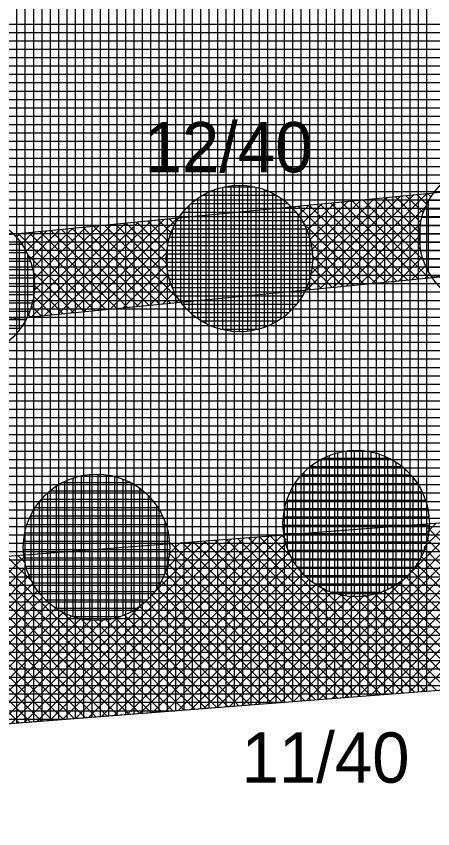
# Model space of a CAD drawing. Extents: x -566461 to -565198, y -1096301 to -1095707.
# Drawn here: x -566318.3 to -566308.34, y -1095862.29 to -1095842.88 of the extents above; entities that cross this region are included whole.
import ezdxf

# ---------------------------------------------------------------- set-up
doc = ezdxf.new("R2010")
doc.units = 0
for name, color, linetype in [('Vrstva 1', 7, 'Continuous'), ('Vrstva 40', 7, 'Continuous'), ('Vrstva 41', 7, 'Continuous'), ('Vrstva 42', 7, 'Continuous'), ('Vrstva 43', 7, 'Continuous'), ('Vrstva 44', 7, 'Continuous')]:
    doc.layers.add(name, color=color, linetype=linetype)

msp = doc.modelspace()

# ---------------------------------------------------------------- linework, layer by layer
at = {"layer": 'Vrstva 1'}
msp.add_line((-566351.09, -1095862.29), (-566300.24, -1095858.37), dxfattribs=at)
at = {"layer": 'Vrstva 41'}
for p, q in [((-566308.802, -1095847.155), (-566311.03, -1095849.384)), ((-566308.488, -1095847.125), (-566310.716, -1095849.353)), ((-566308.714, -1095847.147), (-566308.478, -1095847.384)), ((-566308.457, -1095847.122), (-566308.376, -1095847.202)), ((-566310.683, -1095847.339), (-566311.352, -1095848.009)), ((-566309.115, -1095847.186), (-566311.343, -1095849.414)), ((-566310.369, -1095847.309), (-566311.281, -1095848.221)), ((-566309.429, -1095847.217), (-566311.263, -1095849.051)), ((-566310.056, -1095847.278), (-566311.234, -1095848.456)), ((-566309.742, -1095847.247), (-566311.226, -1095848.732)), ((-566310.775, -1095847.348), (-566308.944, -1095849.18)), ((-566310.518, -1095847.323), (-566308.687, -1095849.154)), ((-566310.26, -1095847.298), (-566308.429, -1095849.129)), ((-566310.003, -1095847.273), (-566308.55, -1095848.725)), ((-566309.745, -1095847.248), (-566308.638, -1095848.355)), ((-566309.487, -1095847.222), (-566308.649, -1095848.061)), ((-566309.23, -1095847.197), (-566308.62, -1095847.807)), ((-566308.972, -1095847.172), (-566308.561, -1095847.583)), ((-566311.623, -1095847.431), (-566311.682, -1095847.491)), ((-566311.31, -1095847.401), (-566311.554, -1095847.645)), ((-566311.548, -1095847.424), (-566309.717, -1095849.255)), ((-566310.996, -1095847.37), (-566311.444, -1095847.818)), ((-566311.291, -1095847.399), (-566309.46, -1095849.23)), ((-566311.033, -1095847.374), (-566309.202, -1095849.205)), ((-566308.492, -1095847.411), (-566310.403, -1095849.322)), ((-566314.758, -1095847.738), (-566316.986, -1095849.966)), ((-566314.444, -1095847.707), (-566316.672, -1095849.935)), ((-566314.64, -1095847.726), (-566314.501, -1095847.866)), ((-566316.012, -1095847.86), (-566317.939, -1095849.787)), ((-566315.698, -1095847.83), (-566317.926, -1095850.058)), ((-566316.325, -1095847.891), (-566317.885, -1095849.45)), ((-566316.639, -1095847.922), (-566317.878, -1095849.161)), ((-566315.385, -1095847.799), (-566317.613, -1095850.027)), ((-566315.071, -1095847.768), (-566317.299, -1095849.996)), ((-566316.702, -1095847.928), (-566314.87, -1095849.759)), ((-566316.444, -1095847.903), (-566314.613, -1095849.734)), ((-566316.186, -1095847.877), (-566314.356, -1095849.707)), ((-566315.929, -1095847.852), (-566314.63, -1095849.15)), ((-566315.671, -1095847.827), (-566314.693, -1095848.805)), ((-566315.413, -1095847.802), (-566314.693, -1095848.522)), ((-566315.156, -1095847.777), (-566314.654, -1095848.278)), ((-566314.898, -1095847.751), (-566314.588, -1095848.061)), ((-566311.451, -1095847.805), (-566309.975, -1095849.28)), ((-566308.622, -1095847.825), (-566310.089, -1095849.292)), ((-566318.206, -1095848.075), (-566318.299, -1095848.168)), ((-566318.248, -1095848.079), (-566316.416, -1095849.91)), ((-566317.893, -1095848.044), (-566318.176, -1095848.327)), ((-566317.579, -1095848.014), (-566318.07, -1095848.504)), ((-566317.99, -1095848.054), (-566316.159, -1095849.885)), ((-566317.266, -1095847.983), (-566317.983, -1095848.7)), ((-566316.952, -1095847.952), (-566317.916, -1095848.916)), ((-566317.732, -1095848.028), (-566315.901, -1095849.86)), ((-566317.475, -1095848.003), (-566315.643, -1095849.834)), ((-566317.217, -1095847.978), (-566315.386, -1095849.809)), ((-566316.959, -1095847.953), (-566315.128, -1095849.784)), ((-566314.625, -1095848.171), (-566316.359, -1095849.904)), ((-566311.268, -1095848.27), (-566310.233, -1095849.306)), ((-566308.653, -1095848.138), (-566309.776, -1095849.261)), ((-566308.631, -1095848.399), (-566309.462, -1095849.23)), ((-566318.033, -1095848.576), (-566316.674, -1095849.935)), ((-566314.693, -1095848.521), (-566316.045, -1095849.874)), ((-566311.224, -1095848.597), (-566310.49, -1095849.331)), ((-566308.581, -1095848.631), (-566309.149, -1095849.2)), ((-566314.693, -1095848.804), (-566315.732, -1095849.843)), ((-566311.24, -1095848.863), (-566310.748, -1095849.356)), ((-566308.506, -1095848.839), (-566308.835, -1095849.169)), ((-566317.901, -1095848.991), (-566316.932, -1095849.96)), ((-566314.657, -1095849.051), (-566315.419, -1095849.812)), ((-566308.409, -1095849.026), (-566308.522, -1095849.138)), ((-566314.592, -1095849.269), (-566315.105, -1095849.782)), ((-566311.278, -1095849.108), (-566311.006, -1095849.381)), ((-566317.87, -1095849.305), (-566317.189, -1095849.986)), ((-566314.505, -1095849.465), (-566314.792, -1095849.751)), ((-566311.348, -1095849.321), (-566311.263, -1095849.406)), ((-566317.896, -1095849.561), (-566317.447, -1095850.011)), ((-566314.4, -1095849.643), (-566314.478, -1095849.721)), ((-566317.942, -1095849.799), (-566317.705, -1095850.036)), ((-566318.016, -1095850.007), (-566317.962, -1095850.061)), ((-566307.033, -1095854.9), (-566311.36, -1095859.227)), ((-566306.727, -1095854.877), (-566311.053, -1095859.204)), ((-566306.42, -1095854.853), (-566310.747, -1095859.18)), ((-566306.114, -1095854.83), (-566310.44, -1095859.156)), ((-566305.807, -1095854.806), (-566310.134, -1095859.133)), ((-566307.646, -1095854.948), (-566311.973, -1095859.274)), ((-566307.339, -1095854.924), (-566311.666, -1095859.251)), ((-566305.725, -1095855.007), (-566309.827, -1095859.109)), ((-566307.952, -1095854.971), (-566308.544, -1095855.563)), ((-566308.259, -1095854.995), (-566308.469, -1095855.205)), ((-566308.459, -1095855.103), (-566304.837, -1095858.724)), ((-566312.243, -1095855.302), (-566316.57, -1095859.629)), ((-566311.936, -1095855.278), (-566316.263, -1095859.605)), ((-566312.221, -1095855.3), (-566311.664, -1095855.858)), ((-566311.958, -1095855.28), (-566311.846, -1095855.393)), ((-566305.656, -1095855.221), (-566309.521, -1095859.085)), ((-566313.469, -1095855.397), (-566317.796, -1095859.723)), ((-566313.162, -1095855.373), (-566317.489, -1095859.7)), ((-566312.856, -1095855.349), (-566317.183, -1095859.676)), ((-566312.549, -1095855.326), (-566316.876, -1095859.652)), ((-566311.829, -1095855.454), (-566315.957, -1095859.582)), ((-566313.775, -1095855.42), (-566315.074, -1095856.719)), ((-566314.082, -1095855.444), (-566314.717, -1095856.079)), ((-566314.388, -1095855.467), (-566314.658, -1095855.737)), ((-566314.584, -1095855.483), (-566310.877, -1095859.19)), ((-566314.322, -1095855.462), (-566310.614, -1095859.17)), ((-566314.059, -1095855.442), (-566310.352, -1095859.15)), ((-566313.797, -1095855.422), (-566310.089, -1095859.129)), ((-566313.534, -1095855.402), (-566309.827, -1095859.109)), ((-566313.271, -1095855.381), (-566309.564, -1095859.089)), ((-566313.009, -1095855.361), (-566309.301, -1095859.069)), ((-566312.746, -1095855.341), (-566309.039, -1095859.048)), ((-566312.484, -1095855.321), (-566308.776, -1095859.028)), ((-566305.566, -1095855.413), (-566309.214, -1095859.062)), ((-566308.485, -1095855.359), (-566305.1, -1095858.745)), ((-566311.757, -1095855.665), (-566315.65, -1095859.558)), ((-566314.653, -1095855.697), (-566311.14, -1095859.21)), ((-566305.457, -1095855.587), (-566308.908, -1095859.038)), ((-566308.55, -1095855.578), (-566305.362, -1095858.765)), ((-566318.105, -1095855.79), (-566322.393, -1095860.078)), ((-566319.836, -1095855.887), (-566316.129, -1095859.595)), ((-566319.574, -1095855.867), (-566315.866, -1095859.575)), ((-566319.311, -1095855.847), (-566315.604, -1095859.554)), ((-566319.049, -1095855.827), (-566315.341, -1095859.534)), ((-566318.786, -1095855.806), (-566315.079, -1095859.514)), ((-566318.523, -1095855.786), (-566317.905, -1095856.404)), ((-566318.261, -1095855.766), (-566318.077, -1095855.949)), ((-566311.665, -1095855.855), (-566315.344, -1095859.534)), ((-566308.635, -1095855.775), (-566305.625, -1095858.785)), ((-566305.33, -1095855.743), (-566308.602, -1095859.015)), ((-566318.057, -1095856.025), (-566322.086, -1095860.054)), ((-566321.412, -1095856.009), (-566317.705, -1095859.716)), ((-566321.149, -1095855.989), (-566317.442, -1095859.696)), ((-566320.887, -1095855.968), (-566317.179, -1095859.676)), ((-566320.624, -1095855.948), (-566316.917, -1095859.656)), ((-566320.362, -1095855.928), (-566316.654, -1095859.635)), ((-566320.099, -1095855.908), (-566316.392, -1095859.615)), ((-566311.552, -1095856.025), (-566315.037, -1095859.511)), ((-566314.683, -1095855.95), (-566311.402, -1095859.23)), ((-566308.739, -1095855.954), (-566305.888, -1095858.805)), ((-566317.986, -1095856.237), (-566321.78, -1095860.03)), ((-566321.472, -1095856.232), (-566317.967, -1095859.737)), ((-566314.748, -1095856.168), (-566311.665, -1095859.251)), ((-566311.423, -1095856.179), (-566314.731, -1095859.487)), ((-566308.998, -1095856.26), (-566306.413, -1095858.846)), ((-566308.86, -1095856.115), (-566306.15, -1095858.826)), ((-566321.524, -1095856.463), (-566318.23, -1095859.757)), ((-566317.894, -1095856.427), (-566321.473, -1095860.007)), ((-566314.834, -1095856.364), (-566311.927, -1095859.271)), ((-566311.277, -1095856.316), (-566314.424, -1095859.463)), ((-566311.115, -1095856.437), (-566314.118, -1095859.44)), ((-566309.153, -1095856.389), (-566306.675, -1095858.866)), ((-566317.783, -1095856.599), (-566321.167, -1095859.983)), ((-566314.939, -1095856.542), (-566312.19, -1095859.291)), ((-566310.936, -1095856.54), (-566313.811, -1095859.416)), ((-566310.737, -1095856.625), (-566313.505, -1095859.393)), ((-566309.607, -1095856.626), (-566312.279, -1095859.298)), ((-566311.028, -1095856.494), (-566308.514, -1095859.008)), ((-566309.728, -1095856.662), (-566307.463, -1095858.927)), ((-566309.516, -1095856.591), (-566307.201, -1095858.907)), ((-566309.324, -1095856.5), (-566306.938, -1095858.886)), ((-566317.654, -1095856.754), (-566320.86, -1095859.96)), ((-566315.199, -1095856.847), (-566312.715, -1095859.332)), ((-566315.061, -1095856.703), (-566312.453, -1095859.311)), ((-566310.516, -1095856.687), (-566313.199, -1095859.369)), ((-566310.264, -1095856.717), (-566312.892, -1095859.345)), ((-566309.974, -1095856.711), (-566312.586, -1095859.322)), ((-566310.563, -1095856.676), (-566308.251, -1095858.988)), ((-566310.237, -1095856.719), (-566307.988, -1095858.967)), ((-566309.964, -1095856.709), (-566307.726, -1095858.947)), ((-566317.51, -1095856.892), (-566320.554, -1095859.936)), ((-566317.348, -1095857.013), (-566320.247, -1095859.912)), ((-566315.231, -1095856.876), (-566318.102, -1095859.747)), ((-566315.354, -1095856.976), (-566312.978, -1095859.352)), ((-566317.17, -1095857.118), (-566319.941, -1095859.889)), ((-566316.973, -1095857.204), (-566319.634, -1095859.865)), ((-566315.871, -1095857.233), (-566318.409, -1095859.771)), ((-566317.214, -1095857.095), (-566314.816, -1095859.494)), ((-566315.93, -1095857.248), (-566313.766, -1095859.413)), ((-566315.718, -1095857.178), (-566313.503, -1095859.392)), ((-566315.527, -1095857.086), (-566313.24, -1095859.372)), ((-566316.755, -1095857.269), (-566319.328, -1095859.841)), ((-566316.507, -1095857.304), (-566319.021, -1095859.818)), ((-566316.223, -1095857.302), (-566318.715, -1095859.794)), ((-566316.759, -1095857.267), (-566314.553, -1095859.473)), ((-566316.437, -1095857.307), (-566314.291, -1095859.453)), ((-566316.165, -1095857.296), (-566314.028, -1095859.433))]:
    msp.add_line(p, q, dxfattribs=at)
at = {"layer": 'Vrstva 42'}
for points in [[(-566353.532, -1095851.528), (-566353.085, -1095853.494), (-566302.553, -1095848.555), (-566303.017, -1095846.59)], [(-566351.98, -1095858.365), (-566351.09, -1095862.29), (-566300.24, -1095858.37), (-566301.163, -1095854.448)]]:
    msp.add_lwpolyline(points, close=True, dxfattribs=at)
at = {"layer": 'Vrstva 43'}
for p, q in [((-566309.09, -1095837.638), (-566309.09, -1095859.052)), ((-566308.89, -1095837.619), (-566308.89, -1095859.037)), ((-566308.69, -1095837.599), (-566308.69, -1095859.021)), ((-566308.49, -1095837.58), (-566308.49, -1095859.006)), ((-566311.09, -1095837.834), (-566311.09, -1095859.206)), ((-566310.89, -1095837.814), (-566310.89, -1095859.191)), ((-566310.69, -1095837.795), (-566310.69, -1095859.176)), ((-566310.49, -1095837.775), (-566310.49, -1095859.16)), ((-566310.29, -1095837.756), (-566310.29, -1095859.145)), ((-566310.09, -1095837.736), (-566310.09, -1095859.129)), ((-566309.89, -1095837.717), (-566309.89, -1095859.114)), ((-566309.69, -1095837.697), (-566309.69, -1095859.098)), ((-566309.49, -1095837.677), (-566309.49, -1095859.083)), ((-566309.29, -1095837.658), (-566309.29, -1095859.068)), ((-566313.09, -1095838.029), (-566313.09, -1095859.361)), ((-566312.89, -1095838.01), (-566312.89, -1095859.345)), ((-566312.69, -1095837.99), (-566312.69, -1095859.33)), ((-566312.49, -1095837.971), (-566312.49, -1095859.314)), ((-566312.29, -1095837.951), (-566312.29, -1095859.299)), ((-566312.09, -1095837.932), (-566312.09, -1095859.284)), ((-566311.89, -1095837.912), (-566311.89, -1095859.268)), ((-566311.69, -1095837.893), (-566311.69, -1095859.253)), ((-566311.49, -1095837.873), (-566311.49, -1095859.237)), ((-566311.29, -1095837.853), (-566311.29, -1095859.222)), ((-566315.09, -1095838.225), (-566315.09, -1095859.515)), ((-566314.89, -1095838.205), (-566314.89, -1095859.499)), ((-566314.69, -1095838.186), (-566314.69, -1095859.484)), ((-566314.49, -1095838.166), (-566314.49, -1095859.469)), ((-566314.29, -1095838.147), (-566314.29, -1095859.453)), ((-566314.09, -1095838.127), (-566314.09, -1095859.438)), ((-566313.89, -1095838.108), (-566313.89, -1095859.422)), ((-566313.69, -1095838.088), (-566313.69, -1095859.407)), ((-566313.49, -1095838.068), (-566313.49, -1095859.391)), ((-566313.29, -1095838.049), (-566313.29, -1095859.376)), ((-566317.09, -1095838.42), (-566317.09, -1095859.669)), ((-566316.89, -1095838.401), (-566316.89, -1095859.654)), ((-566316.69, -1095838.381), (-566316.69, -1095859.638)), ((-566316.49, -1095838.362), (-566316.49, -1095859.623)), ((-566316.29, -1095838.342), (-566316.29, -1095859.607)), ((-566316.09, -1095838.323), (-566316.09, -1095859.592)), ((-566315.89, -1095838.303), (-566315.89, -1095859.576)), ((-566315.69, -1095838.284), (-566315.69, -1095859.561)), ((-566315.49, -1095838.264), (-566315.49, -1095859.546)), ((-566315.29, -1095838.244), (-566315.29, -1095859.53)), ((-566318.29, -1095838.538), (-566318.29, -1095859.761)), ((-566318.09, -1095838.518), (-566318.09, -1095859.746)), ((-566317.89, -1095838.499), (-566317.89, -1095859.731)), ((-566317.69, -1095838.479), (-566317.69, -1095859.715)), ((-566317.49, -1095838.46), (-566317.49, -1095859.7)), ((-566317.29, -1095838.44), (-566317.29, -1095859.684)), ((-566355.45, -1095843.07), (-566303.849, -1095843.07)), ((-566355.405, -1095843.27), (-566303.802, -1095843.27)), ((-566355.36, -1095843.47), (-566303.755, -1095843.47)), ((-566355.314, -1095843.67), (-566303.708, -1095843.67)), ((-566355.269, -1095843.87), (-566303.661, -1095843.87)), ((-566355.223, -1095844.07), (-566303.613, -1095844.07)), ((-566355.178, -1095844.27), (-566303.566, -1095844.27)), ((-566355.133, -1095844.47), (-566303.519, -1095844.47)), ((-566355.087, -1095844.67), (-566303.472, -1095844.67)), ((-566355.042, -1095844.87), (-566303.425, -1095844.87)), ((-566354.997, -1095845.07), (-566303.378, -1095845.07)), ((-566354.951, -1095845.27), (-566303.33, -1095845.27)), ((-566354.906, -1095845.47), (-566303.283, -1095845.47)), ((-566354.861, -1095845.67), (-566303.236, -1095845.67)), ((-566354.815, -1095845.87), (-566303.189, -1095845.87)), ((-566354.77, -1095846.07), (-566303.142, -1095846.07)), ((-566354.724, -1095846.27), (-566303.094, -1095846.27)), ((-566354.679, -1095846.47), (-566303.047, -1095846.47)), ((-566354.634, -1095846.67), (-566303, -1095846.67)), ((-566354.588, -1095846.87), (-566302.953, -1095846.87)), ((-566354.543, -1095847.07), (-566302.906, -1095847.07)), ((-566354.498, -1095847.27), (-566302.859, -1095847.27)), ((-566354.452, -1095847.47), (-566302.811, -1095847.47)), ((-566354.407, -1095847.67), (-566302.764, -1095847.67)), ((-566354.361, -1095847.87), (-566302.717, -1095847.87)), ((-566354.316, -1095848.07), (-566302.67, -1095848.07)), ((-566354.271, -1095848.27), (-566302.623, -1095848.27)), ((-566354.225, -1095848.47), (-566302.575, -1095848.47)), ((-566354.18, -1095848.67), (-566302.528, -1095848.67)), ((-566354.135, -1095848.87), (-566302.481, -1095848.87)), ((-566354.089, -1095849.07), (-566302.434, -1095849.07)), ((-566354.044, -1095849.27), (-566302.387, -1095849.27)), ((-566353.998, -1095849.47), (-566302.34, -1095849.47)), ((-566353.953, -1095849.67), (-566302.292, -1095849.67)), ((-566353.908, -1095849.87), (-566302.245, -1095849.87)), ((-566353.862, -1095850.07), (-566302.198, -1095850.07)), ((-566353.817, -1095850.27), (-566302.151, -1095850.27)), ((-566353.772, -1095850.47), (-566302.104, -1095850.47)), ((-566353.726, -1095850.67), (-566302.056, -1095850.67)), ((-566353.681, -1095850.87), (-566302.009, -1095850.87)), ((-566353.635, -1095851.07), (-566301.962, -1095851.07)), ((-566353.59, -1095851.27), (-566301.915, -1095851.27)), ((-566353.545, -1095851.47), (-566301.868, -1095851.47)), ((-566353.499, -1095851.67), (-566301.821, -1095851.67)), ((-566353.454, -1095851.87), (-566301.773, -1095851.87)), ((-566353.409, -1095852.07), (-566301.726, -1095852.07)), ((-566353.363, -1095852.27), (-566301.679, -1095852.27)), ((-566353.318, -1095852.47), (-566301.632, -1095852.47)), ((-566353.272, -1095852.67), (-566301.585, -1095852.67)), ((-566353.227, -1095852.87), (-566301.537, -1095852.87)), ((-566353.182, -1095853.07), (-566301.49, -1095853.07)), ((-566353.136, -1095853.27), (-566301.443, -1095853.27)), ((-566353.091, -1095853.47), (-566301.396, -1095853.47)), ((-566353.046, -1095853.67), (-566301.349, -1095853.67)), ((-566353, -1095853.87), (-566301.302, -1095853.87)), ((-566352.955, -1095854.07), (-566301.254, -1095854.07)), ((-566352.909, -1095854.27), (-566301.207, -1095854.27)), ((-566352.864, -1095854.47), (-566301.16, -1095854.47)), ((-566352.819, -1095854.67), (-566301.113, -1095854.67)), ((-566352.773, -1095854.87), (-566301.066, -1095854.87)), ((-566352.728, -1095855.07), (-566301.018, -1095855.07)), ((-566352.683, -1095855.27), (-566300.971, -1095855.27)), ((-566352.637, -1095855.47), (-566300.924, -1095855.47)), ((-566352.592, -1095855.67), (-566300.877, -1095855.67)), ((-566352.546, -1095855.87), (-566300.83, -1095855.87)), ((-566352.501, -1095856.07), (-566300.783, -1095856.07)), ((-566352.456, -1095856.27), (-566300.735, -1095856.27)), ((-566352.41, -1095856.47), (-566300.688, -1095856.47)), ((-566352.365, -1095856.67), (-566300.641, -1095856.67)), ((-566352.32, -1095856.87), (-566300.594, -1095856.87)), ((-566352.274, -1095857.07), (-566300.547, -1095857.07)), ((-566352.229, -1095857.27), (-566300.499, -1095857.27)), ((-566352.183, -1095857.47), (-566300.452, -1095857.47)), ((-566352.138, -1095857.67), (-566300.405, -1095857.67)), ((-566352.093, -1095857.87), (-566300.358, -1095857.87)), ((-566352.047, -1095858.07), (-566300.311, -1095858.07)), ((-566352.002, -1095858.27), (-566300.264, -1095858.27)), ((-566351.957, -1095858.47), (-566301.537, -1095858.47)), ((-566351.911, -1095858.67), (-566304.132, -1095858.67)), ((-566351.866, -1095858.87), (-566306.726, -1095858.87)), ((-566351.821, -1095859.07), (-566309.32, -1095859.07)), ((-566351.775, -1095859.27), (-566311.915, -1095859.27)), ((-566351.73, -1095859.47), (-566314.509, -1095859.47)), ((-566351.684, -1095859.67), (-566317.104, -1095859.67))]:
    msp.add_line(p, q, dxfattribs=at)
msp.add_lwpolyline([(-566355.65, -1095842.19), (-566351.09, -1095862.29), (-566300.24, -1095858.37), (-566305.22, -1095837.26)], close=True, dxfattribs=at)
at = {"layer": 'Vrstva 44'}
for p, q in [((-566313.324, -1095846.96), (-566312.591, -1095846.96)), ((-566313.16, -1095850.408), (-566313.16, -1095846.933)), ((-566312.96, -1095850.418), (-566312.96, -1095846.921)), ((-566312.76, -1095850.407), (-566312.76, -1095846.932)), ((-566313.841, -1095847.16), (-566312.079, -1095847.16)), ((-566313.76, -1095850.226), (-566313.76, -1095847.114)), ((-566313.56, -1095850.312), (-566313.56, -1095847.027)), ((-566313.36, -1095850.373), (-566313.36, -1095846.968)), ((-566312.56, -1095850.372), (-566312.56, -1095846.968)), ((-566312.36, -1095850.314), (-566312.36, -1095847.028)), ((-566312.16, -1095850.225), (-566312.16, -1095847.115)), ((-566313.96, -1095850.104), (-566313.96, -1095847.236)), ((-566311.96, -1095850.104), (-566311.96, -1095847.236)), ((-566308.44, -1095848.988), (-566308.44, -1095847.294)), ((-566308.433, -1095847.28), (-566305.387, -1095847.28)), ((-566314.16, -1095849.943), (-566314.16, -1095847.397)), ((-566314.118, -1095847.36), (-566311.803, -1095847.36)), ((-566311.76, -1095849.942), (-566311.76, -1095847.398)), ((-566308.529, -1095847.48), (-566305.291, -1095847.48)), ((-566314.36, -1095849.717), (-566314.36, -1095847.622)), ((-566314.31, -1095847.56), (-566311.608, -1095847.56)), ((-566311.56, -1095849.72), (-566311.56, -1095847.623)), ((-566308.597, -1095847.68), (-566305.224, -1095847.68)), ((-566314.454, -1095847.76), (-566311.468, -1095847.76)), ((-566308.64, -1095848.398), (-566308.64, -1095847.877)), ((-566308.64, -1095847.88), (-566305.181, -1095847.88)), ((-566314.56, -1095849.378), (-566314.56, -1095847.965)), ((-566314.558, -1095847.96), (-566311.361, -1095847.96)), ((-566311.36, -1095849.374), (-566311.36, -1095847.962)), ((-566308.658, -1095848.08), (-566305.162, -1095848.08)), ((-566318.22, -1095850.372), (-566318.22, -1095848.25)), ((-566314.632, -1095848.16), (-566311.287, -1095848.16)), ((-566308.652, -1095848.28), (-566305.166, -1095848.28)), ((-566321.058, -1095848.33), (-566318.161, -1095848.33)), ((-566314.681, -1095848.36), (-566311.24, -1095848.36)), ((-566308.625, -1095848.48), (-566305.195, -1095848.48)), ((-566321.175, -1095848.53), (-566318.046, -1095848.53)), ((-566318.02, -1095850.038), (-566318.02, -1095848.582)), ((-566314.706, -1095848.56), (-566311.215, -1095848.56)), ((-566308.574, -1095848.68), (-566305.247, -1095848.68)), ((-566321.261, -1095848.73), (-566317.961, -1095848.73)), ((-566314.707, -1095848.76), (-566311.214, -1095848.76)), ((-566308.495, -1095848.88), (-566305.325, -1095848.88)), ((-566321.317, -1095848.93), (-566317.902, -1095848.93)), ((-566314.684, -1095848.96), (-566311.234, -1095848.96)), ((-566308.384, -1095849.08), (-566305.435, -1095849.08)), ((-566321.349, -1095849.13), (-566317.871, -1095849.13)), ((-566314.638, -1095849.16), (-566311.282, -1095849.16)), ((-566321.358, -1095849.33), (-566317.862, -1095849.33)), ((-566314.567, -1095849.36), (-566311.354, -1095849.36)), ((-566321.345, -1095849.53), (-566317.876, -1095849.53)), ((-566314.466, -1095849.56), (-566311.454, -1095849.56)), ((-566321.308, -1095849.73), (-566317.912, -1095849.73)), ((-566314.327, -1095849.76), (-566311.593, -1095849.76)), ((-566321.245, -1095849.93), (-566317.974, -1095849.93)), ((-566314.14, -1095849.96), (-566311.778, -1095849.96)), ((-566321.154, -1095850.13), (-566318.066, -1095850.13)), ((-566313.875, -1095850.16), (-566312.043, -1095850.16)), ((-566321.031, -1095850.33), (-566318.19, -1095850.33)), ((-566313.411, -1095850.36), (-566312.507, -1095850.36)), ((-566310.61, -1095856.693), (-566310.61, -1095853.308)), ((-566310.41, -1095856.732), (-566310.41, -1095853.268)), ((-566310.21, -1095856.749), (-566310.21, -1095853.252)), ((-566310.01, -1095856.741), (-566310.01, -1095853.259)), ((-566309.81, -1095856.711), (-566309.81, -1095853.288)), ((-566309.61, -1095856.656), (-566309.61, -1095853.344)), ((-566311.01, -1095856.534), (-566311.01, -1095853.467)), ((-566310.962, -1095853.44), (-566309.38, -1095853.44)), ((-566310.81, -1095856.628), (-566310.81, -1095853.372)), ((-566309.41, -1095856.576), (-566309.41, -1095853.426)), ((-566309.21, -1095856.461), (-566309.21, -1095853.537)), ((-566311.269, -1095853.64), (-566309.069, -1095853.64)), ((-566311.21, -1095856.405), (-566311.21, -1095853.594)), ((-566309.01, -1095856.309), (-566309.01, -1095853.692)), ((-566316.94, -1095857.226), (-566316.94, -1095853.914)), ((-566316.74, -1095857.282), (-566316.74, -1095853.859)), ((-566316.54, -1095857.311), (-566316.54, -1095853.828)), ((-566316.34, -1095857.318), (-566316.34, -1095853.821)), ((-566316.14, -1095857.302), (-566316.14, -1095853.838)), ((-566315.94, -1095857.263), (-566315.94, -1095853.878)), ((-566315.74, -1095857.197), (-566315.74, -1095853.943)), ((-566311.48, -1095853.84), (-566308.862, -1095853.84)), ((-566311.41, -1095856.233), (-566311.41, -1095853.768)), ((-566308.81, -1095856.098), (-566308.81, -1095853.9)), ((-566317.34, -1095857.033), (-566317.34, -1095854.108)), ((-566317.19, -1095854.02), (-566315.569, -1095854.02)), ((-566317.14, -1095857.145), (-566317.14, -1095853.995)), ((-566315.54, -1095857.103), (-566315.54, -1095854.036)), ((-566311.631, -1095854.04), (-566308.708, -1095854.04)), ((-566311.61, -1095855.993), (-566311.61, -1095854.008)), ((-566317.54, -1095856.878), (-566317.54, -1095854.262)), ((-566317.491, -1095854.22), (-566315.267, -1095854.22)), ((-566315.34, -1095856.977), (-566315.34, -1095854.165)), ((-566315.14, -1095856.802), (-566315.14, -1095854.336)), ((-566311.745, -1095854.24), (-566308.596, -1095854.24)), ((-566308.61, -1095855.79), (-566308.61, -1095854.211)), ((-566317.74, -1095856.669), (-566317.74, -1095854.472)), ((-566317.698, -1095854.42), (-566315.063, -1095854.42)), ((-566311.827, -1095854.44), (-566308.513, -1095854.44)), ((-566311.81, -1095855.606), (-566311.81, -1095854.392)), ((-566317.847, -1095854.62), (-566314.912, -1095854.62)), ((-566314.94, -1095856.561), (-566314.94, -1095854.576)), ((-566311.881, -1095854.64), (-566308.458, -1095854.64)), ((-566317.961, -1095854.82), (-566314.801, -1095854.82)), ((-566317.94, -1095856.359), (-566317.94, -1095854.781)), ((-566311.911, -1095854.84), (-566308.429, -1095854.84)), ((-566318.04, -1095855.02), (-566314.719, -1095855.02)), ((-566314.74, -1095856.181), (-566314.74, -1095854.965)), ((-566311.918, -1095855.04), (-566308.422, -1095855.04)), ((-566318.093, -1095855.22), (-566314.667, -1095855.22)), ((-566311.903, -1095855.24), (-566308.438, -1095855.24)), ((-566318.122, -1095855.42), (-566314.638, -1095855.42)), ((-566311.862, -1095855.44), (-566308.477, -1095855.44)), ((-566318.128, -1095855.62), (-566314.633, -1095855.62)), ((-566311.797, -1095855.64), (-566308.543, -1095855.64)), ((-566318.112, -1095855.82), (-566314.649, -1095855.82)), ((-566311.704, -1095855.84), (-566308.637, -1095855.84)), ((-566318.069, -1095856.02), (-566314.689, -1095856.02)), ((-566311.576, -1095856.04), (-566308.763, -1095856.04)), ((-566318.003, -1095856.22), (-566314.757, -1095856.22)), ((-566311.403, -1095856.24), (-566308.938, -1095856.24)), ((-566317.909, -1095856.42), (-566314.853, -1095856.42)), ((-566311.161, -1095856.44), (-566309.179, -1095856.44)), ((-566317.778, -1095856.62), (-566314.98, -1095856.62)), ((-566310.776, -1095856.64), (-566309.56, -1095856.64)), ((-566317.604, -1095856.82), (-566315.158, -1095856.82)), ((-566317.357, -1095857.02), (-566315.404, -1095857.02)), ((-566316.957, -1095857.22), (-566315.8, -1095857.22))]:
    msp.add_line(p, q, dxfattribs=at)
for centre in [(-566306.91, -1095848.14), (-566312.96, -1095848.67), (-566319.61, -1095849.31), (-566310.17, -1095855), (-566316.38, -1095855.57)]:
    msp.add_circle(centre, 1.75, dxfattribs=at)

# ---------------------------------------------------------------- texts
at = {"layer": 'Vrstva 40'}
for s, p in [('12/40', (-566315.23, -1095846.61)), ('11/40', (-566312.91, -1095861.19))]:
    msp.add_text(s, height=1.2, dxfattribs=at).set_placement(p)

doc.saveas('drawing.dxf')
